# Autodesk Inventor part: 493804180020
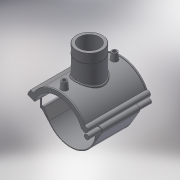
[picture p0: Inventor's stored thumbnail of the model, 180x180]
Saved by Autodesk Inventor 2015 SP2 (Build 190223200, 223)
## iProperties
Created: 2017-07
Part Number: 493804180020
Material: Generic
Description: PLASSON TRANSITION SADDLE 180-2"
Document SubType Name: Modeling
Designer: KIM
Density: 1 g/cm^3
Appearance: Default
Author: KIM
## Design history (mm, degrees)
derived "493804.ipt"
feature "Solid1::493804.ipt"
tag "TaggingFeature1"
body "Solid1"
other parameters: "B_" = 182, "H_" = 76, "L_" = 176, "d_t" = 6, "G_" = 56.656, "d148" = 2.7, "d160" = 2.7, "d169" = 2.7, "d192" = 5.4, "d1" = 207, "d2" = 236.6, "d3" = 45, "d4" = 176, "d5" = 0, "d6" = 0.1, "d8" = 0, "d19" = 6, "d20" = 6, "d21" = 105.6, "d23" = 0, "d24" = 52.8, "d26" = 0, "d27" = 3, "d28" = 3, "d29" = 3, "d31" = 6, "d32" = 0, "d33" = 0, "d34" = 0.6, "d40" = 107.64, "d41" = 79.3184, "d43" = 0, "d45" = 0, "d47" = 179.5, "d48" = 73.6528, "d50" = 0, "d70" = 15, "d72" = 0, "d73" = 6, "d75" = 5, "d76" = 0, "d77" = 9, "d79" = 15, "d80" = 70.4, "d82" = 5 deg, "d84" = 4, "d85" = 14, "d86" = 0, "d87" = 3, "d88" = 0, "d89" = 1, "d90" = 1, "d91" = 140.8, "d92" = 0, "d93" = 0.5, "d94" = 94.73684, "d96" = 211.14, "d97" = 3.52, "d98" = 0, "d102" = 1.69968, "d103" = 56.656, "d104" = 45.6, "d105" = 0, "d106" = 45.3248, "d108" = 0, "d109" = -25.33333, "d111" = 0.5, "d112" = 0.5, "d113" = 0, "d114" = 0.5, "d117" = 0.56656, "d120" = 140 deg, "d121" = 24.228, "d122" = 20 deg, "d123" = 414, "d124" = 124.2, "d126" = 0, "d143" = 185.4, "d145" = 20.76923, "d149" = 2.7, "d150" = 22.84615, "d153" = 176, "d154" = 0, "d156" = 103.5, "d157" = 160 deg, "d159" = 5.4, "d161" = 2.7, "d162" = 105.6, "d163" = 0, "d167" = 18, "d168" = 100.97561, "d170" = 2.7, "d172" = 0, "d173" = 1, "d176" = 20 deg, "d177" = 12.6, "d178" = 27, "d180" = 0, "d183" = 10.8, "d184" = 10.08, "d185" = 57.2, "d186" = 57.2, "d187" = 103.5, "d188" = 8.1, "d189" = 12.6, "d190" = 0, "d191" = 124.2, "d193" = 5.4, "d194" = 4.4, "d195" = 90 deg, "d197" = 0, "d199" = 0
